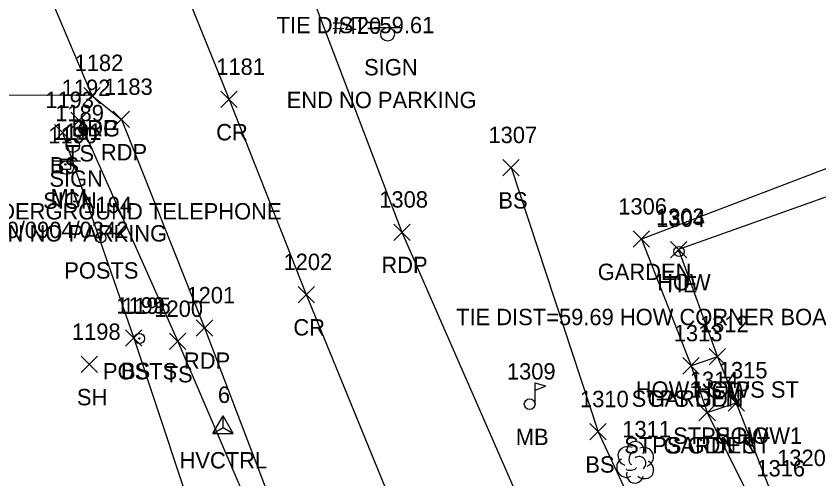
# Model space of a CAD drawing. Extents: x 1651305 to 1654558, y 539481 to 548441.
# Drawn here: x 1654172 to 1654270.1, y 544943.1 to 544999.6 of the extents above; entities that cross this region are included whole.
import ezdxf

# ---------------------------------------------------------------- set-up
doc = ezdxf.new("R2010")
doc.units = 0
for name, color, linetype in [('C_A', 7, 'Continuous'), ('C_C', 7, 'Continuous'), ('C_I', 7, 'Continuous'), ('CBP', 7, 'Continuous'), ('CPSM', 7, 'Continuous'), ('L_A', 7, 'Continuous'), ('L_I', 7, 'Continuous'), ('L_TIC', 7, 'Continuous'), ('LAPB', 7, 'Continuous'), ('LBC', 7, 'Continuous'), ('LBF', 7, 'Continuous'), ('LELB', 7, 'Continuous'), ('LMB', 7, 'Continuous'), ('LPST', 7, 'Continuous'), ('LTD', 7, 'Continuous'), ('P_A', 7, 'Continuous'), ('P_I', 7, 'Continuous'), ('P_TIC', 7, 'Continuous'), ('PET', 7, 'Continuous'), ('PRC', 7, 'Continuous'), ('R_A', 7, 'Continuous'), ('R_I', 7, 'Continuous'), ('R_TIC', 7, 'Continuous'), ('RDG', 7, 'Continuous'), ('S_A', 7, 'Continuous'), ('S_C', 7, 'Continuous'), ('S_I', 7, 'Continuous'), ('SRM', 7, 'Continuous'), ('SSGN', 7, 'Continuous'), ('U_C', 7, 'Continuous')]:
    doc.layers.add(name, color=color, linetype=linetype)

msp = doc.modelspace()

# ---------------------------------------------------------------- linework, layer by layer
at = {"layer": 'CBP'}
for radius in [0.625, 0.0833]:
    msp.add_circle((1654252.972, 544970.875), radius, dxfattribs=at)
at = {"layer": 'CPSM'}
for p, q in [((1654196.041, 544948.65), (1654197.291, 544950.816)), ((1654198.541, 544948.65), (1654197.291, 544950.816)), ((1654197.291, 544949.372), (1654197.291, 544950.816)), ((1654196.041, 544948.65), (1654197.291, 544949.372)), ((1654197.291, 544949.372), (1654197.291, 544949.372)), ((1654197.291, 544949.372), (1654198.541, 544948.65)), ((1654196.041, 544948.65), (1654198.541, 544948.65))]:
    msp.add_line(p, q, dxfattribs=at)
at = {"layer": 'L_TIC'}
for points in [[(1654178.719, 544985.88), (1654180.719, 544987.88)], [(1654180.719, 544985.88), (1654178.719, 544987.88)], [(1654176.711, 544984.406), (1654178.711, 544986.406)], [(1654178.711, 544984.406), (1654176.711, 544986.406)], [(1654231.471, 544980.122), (1654233.471, 544982.122)], [(1654233.471, 544980.122), (1654231.471, 544982.122)], [(1654247.375, 544971.387), (1654249.375, 544973.387)], [(1654249.375, 544971.387), (1654247.375, 544973.387)], [(1654251.913, 544970.116), (1654253.913, 544972.116)], [(1654253.913, 544970.116), (1654251.913, 544972.116)], [(1654185.395, 544959.29), (1654187.395, 544961.29)], [(1654187.395, 544959.29), (1654185.395, 544961.29)], [(1654190.759, 544958.884), (1654192.759, 544960.884)], [(1654192.759, 544958.884), (1654190.759, 544960.884)], [(1654256.648, 544957.011), (1654258.648, 544959.011)], [(1654258.648, 544957.011), (1654256.648, 544959.011)], [(1654256.648, 544957.011), (1654258.648, 544959.011)], [(1654258.648, 544957.011), (1654256.648, 544959.011)], [(1654179.965, 544956.082), (1654181.965, 544958.082)], [(1654181.965, 544956.082), (1654179.965, 544958.082)], [(1654253.449, 544955.905), (1654255.449, 544957.905)], [(1654255.449, 544955.905), (1654253.449, 544957.905)], [(1654253.449, 544955.905), (1654255.449, 544957.905)], [(1654255.449, 544955.905), (1654253.449, 544957.905)], [(1654258.95, 544951.375), (1654260.95, 544953.375)], [(1654260.95, 544951.375), (1654258.95, 544953.375)], [(1654258.95, 544951.375), (1654260.95, 544953.375)], [(1654260.95, 544951.375), (1654258.95, 544953.375)], [(1654255.406, 544950.199), (1654257.406, 544952.199)], [(1654257.406, 544950.199), (1654255.406, 544952.199)], [(1654255.406, 544950.199), (1654257.406, 544952.199)], [(1654257.406, 544950.199), (1654255.406, 544952.199)], [(1654242.092, 544947.856), (1654244.092, 544949.856)], [(1654244.092, 544947.856), (1654242.092, 544949.856)]]:
    msp.add_lwpolyline(points, dxfattribs=at)
at = {"layer": 'LAPB'}
for points in [[(1654280.484, 544984.65), (1654248.375, 544972.387), (1654254.449, 544956.905)], [(1654256.406, 544951.199), (1654262.959, 544938.035), (1654266.98, 544937.971), (1654269.757, 544932.065), (1654277.205, 544934.509)]]:
    msp.add_lwpolyline(points, dxfattribs=at)
at = {"layer": 'LBC'}
msp.add_lwpolyline([(1654281.629, 544981.344), (1654252.913, 544971.116), (1654257.648, 544958.011), (1654259.95, 544952.375), (1654264.598, 544940.395), (1654267.725, 544941.664), (1654270.367, 544934.858), (1654276.314, 544936.878), (1654279.342, 544937.922), (1654288.154, 544941.638), (1654293.107, 544928.35), (1654283.874, 544924.848), (1654288.217, 544913.364), (1654293.485, 544899.631), (1654296.432, 544891.955), (1654318.471, 544900.378)], dxfattribs=at)
at = {"layer": 'LBF'}
msp.add_lwpolyline([(1654257.648, 544958.011), (1654254.449, 544956.905), (1654256.406, 544951.199), (1654259.95, 544952.375)], dxfattribs=at)
at = {"layer": 'LELB'}
for points in [[(1654179.719, 544986.88), (1654191.759, 544959.884), (1654205.631, 544927.6), (1654216.28, 544901.811), (1654236.779, 544849.686), (1654250.25, 544817.938), (1654269.188, 544772.346), (1654285.709, 544732.002), (1654294.184, 544708.026), (1654311.836, 544664.341)], [(1654177.711, 544985.406), (1654186.395, 544960.29), (1654198.077, 544925.069), (1654208.776, 544901.638), (1654231.338, 544847.607), (1654245.847, 544816.464), (1654261.737, 544769.7), (1654274.867, 544730.828), (1654284.44, 544695.192), (1654297.614, 544656.977), (1654309.412, 544642.274)], [(1654232.471, 544981.122), (1654243.092, 544948.856), (1654252.975, 544927.614)]]:
    msp.add_lwpolyline(points, dxfattribs=at)
at = {"layer": 'LMB'}
for p, q in [((1654235.382, 544954.827), (1654236.675, 544954.445)), ((1654235.388, 544952.234), (1654235.386, 544954.829)), ((1654235.386, 544953.927), (1654236.669, 544954.436)), ((1654234.732, 544952.226), (1654234.732, 544952.226))]:
    msp.add_line(p, q, dxfattribs=at)
msp.add_circle((1654234.732, 544952.226), 0.656, dxfattribs=at)
at = {"layer": 'LPST'}
for centre, radius in [((1654182.365, 544972.561), 0.625), ((1654182.365, 544972.561), 0.0833), ((1654187.088, 544960.246), 0.625), ((1654187.088, 544960.246), 0.0833)]:
    msp.add_circle(centre, radius, dxfattribs=at)
at = {"layer": 'LTD'}
msp.add_line((1654247.596, 544945.168), (1654247.596, 544945.168), dxfattribs=at)
msp.add_line((1654247.596, 544945.168), (1654247.596, 544945.168), dxfattribs=at)
msp.add_arc((1654247.642, 544946.602), 1.047, 335.52715, 180.95627, dxfattribs=at)
for centre, major_axis, ratio, start_param, end_param in [((1654246.804, 544945.834), (1.21, -0.512), 0.895232, 1.570796, 4.712389), ((1654248.637, 544945.751), (-1.141, -0.483), 0.949671, 1.570796, 4.712389), ((1654247.387, 544945.626), (-0.208, -0.792), 0.645439, 3.141593, 6.283185), ((1654246.512, 544944.459), (0.584, -1.042), 0.959034, 3.141593, 6.283185), ((1654248.096, 544945.001), (-0.5, 0.667), 0.989748, 3.141593, 6.283185), ((1654248.596, 544944.335), (-1.09, 0.792), 0.841452, 1.570796, 4.712389), ((1654247.137, 544944.418), (-0.625, -0.083), 0.423636, 0, 3.141593), ((1654247.596, 544943.668), (0.265, 1.061), 0.942809, 1.570796, 4.712389)]:
    msp.add_ellipse(centre, major_axis=major_axis, ratio=ratio, start_param=start_param, end_param=end_param, dxfattribs=at)
at = {"layer": 'P_TIC'}
for points in [[(1654180.292, 544988.927), (1654182.292, 544990.927)], [(1654182.292, 544988.927), (1654180.292, 544990.927)], [(1654197.023, 544988.456), (1654199.023, 544990.456)], [(1654199.023, 544988.456), (1654197.023, 544990.456)], [(1654183.888, 544986.01), (1654185.888, 544988.01)], [(1654185.888, 544986.01), (1654183.888, 544988.01)], [(1654218.138, 544972.235), (1654220.138, 544974.235)], [(1654220.138, 544972.235), (1654218.138, 544974.235)], [(1654206.449, 544964.611), (1654208.449, 544966.611)], [(1654208.449, 544964.611), (1654206.449, 544966.611)], [(1654194.032, 544960.541), (1654196.032, 544962.541)], [(1654196.032, 544960.541), (1654194.032, 544962.541)]]:
    msp.add_lwpolyline(points, dxfattribs=at)
at = {"layer": 'PET'}
for points in [[(1654139.13, 545176.501), (1654150.393, 545147.194), (1654157.161, 545131.709), (1654170.764, 545099.134), (1654178.155, 545080.649), (1654186.439, 545060.962), (1654201.827, 545022.365), (1654207.176, 545004.715), (1654219.138, 544973.235), (1654242.36, 544920.072), (1654247.532, 544907.575), (1654259.279, 544878.108), (1654268.455, 544853.759), (1654271.522, 544840.232), (1654282.762, 544813.426), (1654295.449, 544782.265), (1654306.751, 544753.721), (1654320.353, 544717.464), (1654325.712, 544702.64)], [(1654112.873, 545166.538), (1654122.035, 545140.208), (1654132.622, 545111.941), (1654135.362, 545108.194), (1654138.441, 545103.483), (1654151.391, 545069.682), (1654150.584, 545065.43), (1654160.56, 545041.116), (1654174.104, 545006.911), (1654181.292, 544989.927), (1654184.888, 544987.01), (1654195.032, 544961.541), (1654207.758, 544928.164), (1654222.993, 544890.413), (1654239.031, 544850.694), (1654252.069, 544818.679), (1654270.718, 544773.03), (1654287.358, 544732.427), (1654297.759, 544708.463), (1654313.88, 544667.099), (1654319.767, 544684.597), (1654325.712, 544702.64)]]:
    msp.add_lwpolyline(points, dxfattribs=at)
at = {"layer": 'PRC'}
msp.add_lwpolyline([(1654126.316, 545171.737), (1654141.33, 545133.412), (1654151.931, 545107.487), (1654165.206, 545072.693), (1654175.565, 545046.61), (1654188.965, 545011.94), (1654198.023, 544989.456), (1654207.449, 544965.611), (1654220.746, 544933.068), (1654235.659, 544895.022), (1654251.308, 544856.189), (1654265.059, 544822.156), (1654283.023, 544778.205), (1654298.758, 544737.492), (1654308.597, 544712.81), (1654319.767, 544684.597)], dxfattribs=at)
at = {"layer": 'R_TIC'}
for points in [[(1654180.292, 544988.927), (1654182.292, 544990.927)], [(1654182.292, 544988.927), (1654180.292, 544990.927)]]:
    msp.add_lwpolyline(points, dxfattribs=at)
at = {"layer": 'RDG'}
msp.add_lwpolyline([(1654181.292, 544989.927), (1654167.251, 544989.981), (1654154.898, 544987.871), (1654134.518, 544982.897)], dxfattribs=at)
at = {"layer": 'SRM'}
msp.add_lwpolyline([(1654177.431, 544982.142), (1654178.681, 544982.142), (1654178.681, 544980.892), (1654177.431, 544980.892)], close=True, dxfattribs=at)
msp.add_circle((1654178.056, 544981.517), 0.0833, dxfattribs=at)
at = {"layer": 'SSGN'}
for p, q in [((1654215.732, 544998.245), (1654219.065, 544998.245)), ((1654217.379, 544997.412), (1654217.379, 544997.412)), ((1654177.309, 544984.639), (1654180.643, 544984.639)), ((1654178.956, 544983.806), (1654178.956, 544983.806)), ((1654176.549, 544981.949), (1654179.883, 544981.949)), ((1654178.196, 544981.116), (1654178.196, 544981.116))]:
    msp.add_line(p, q, dxfattribs=at)
for centre in [(1654217.379, 544997.412), (1654178.956, 544983.806), (1654178.196, 544981.116)]:
    msp.add_circle(centre, 0.833, dxfattribs=at)

# ---------------------------------------------------------------- texts
at = {"layer": 'C_A'}
for s, p in [('TIE', (1654251.051, 544965.875)), ('HVCTRL', (1654191.984, 544944.372))]:
    msp.add_text(s, height=2, dxfattribs=at).set_placement(p)
at = {"layer": 'C_C'}
for s, p in [('TIE DIST=59.61', (1654203.84, 544997.539)), ('TIE DIST=59.69 HOW CORNER BOARD', (1654225.753, 544961.875))]:
    msp.add_text(s, height=2, dxfattribs=at).set_placement(p)
at = {"layer": 'C_I'}
for s, p in [('1304', (1654250.201, 544973.875)), ('6', (1654196.669, 544952.372))]:
    msp.add_text(s, height=2, dxfattribs=at).set_placement(p)
at = {"layer": 'L_A'}
for s, p in [('TS', (1654178.129, 544981.88)), ('BS', (1654176.152, 544980.406)), ('BS', (1654230.912, 544976.122)), ('POSTS', (1654177.908, 544967.561)), ('GARDEN', (1654243.044, 544967.387)), ('HOW', (1654250.299, 544966.116)), ('POSTS', (1654182.631, 544955.246)), ('BS', (1654184.836, 544955.29)), ('TS', (1654190.168, 544954.884)), ('HOW1 STPS ST', (1654247.688, 544953.011)), ('HOW', (1654255.034, 544953.011)), ('SH', (1654179.453, 544952.082)), ('STPS GDN', (1654247.182, 544951.905)), ('GARDEN', (1654249.119, 544951.905)), ('MB', (1654233.039, 544947.226)), ('STPS HOW1', (1654252.249, 544947.375)), ('HOW', (1654257.336, 544947.375)), ('STPS GDN ST', (1654246.272, 544946.199)), ('GARDEN', (1654251.075, 544946.199)), ('BS', (1654241.533, 544943.856))]:
    msp.add_text(s, height=2, dxfattribs=at).set_placement(p)
at = {"layer": 'L_I'}
for s, p in [('1192', (1654177.594, 544989.88)), ('1193', (1654175.585, 544988.406)), ('1307', (1654229.7, 544984.122)), ('1194', (1654180.239, 544975.561)), ('1306', (1654245.548, 544975.387)), ('1303', (1654250.141, 544974.116)), ('1199', (1654184.262, 544963.29)), ('1195', (1654184.962, 544963.246)), ('1200', (1654188.901, 544962.884)), ('1312', (1654255.522, 544961.011)), ('1312', (1654255.522, 544961.011)), ('1198', (1654178.84, 544960.082)), ('1313', (1654252.324, 544959.905)), ('1313', (1654252.324, 544959.905)), ('1309', (1654231.952, 544955.226)), ('1315', (1654257.825, 544955.375)), ('1315', (1654257.825, 544955.375)), ('1314', (1654254.28, 544954.199)), ('1314', (1654254.28, 544954.199)), ('1310', (1654240.879, 544951.856)), ('1311', (1654246.037, 544948.168)), ('1320', (1654264.946, 544944.664)), ('1316', (1654262.417, 544943.395))]:
    msp.add_text(s, height=2, dxfattribs=at).set_placement(p)
at = {"layer": 'P_A'}
for s, p in [('RDP', (1654178.78, 544984.927)), ('CR', (1654196.456, 544984.456)), ('RDP', (1654182.376, 544982.01)), ('RDP', (1654216.627, 544968.235)), ('CR', (1654205.882, 544960.611)), ('RDP', (1654192.521, 544956.541))]:
    msp.add_text(s, height=2, dxfattribs=at).set_placement(p)
at = {"layer": 'P_I'}
for s, p in [('1182', (1654179.166, 544992.927)), ('1181', (1654196.464, 544992.456)), ('1183', (1654182.762, 544990.01)), ('1308', (1654216.367, 544976.235)), ('1202', (1654204.678, 544968.611)), ('1201', (1654192.828, 544964.541))]:
    msp.add_text(s, height=2, dxfattribs=at).set_placement(p)
at = {"layer": 'R_A'}
msp.add_text('DRG', height=2, dxfattribs=at).set_placement((1654178.78, 544984.927))
at = {"layer": 'R_I'}
msp.add_text('1182', height=2, dxfattribs=at).set_placement((1654179.166, 544992.927))
at = {"layer": 'S_A'}
for s, p in [('SIGN', (1654214.517, 544992.391)), ('SIGN', (1654176.094, 544978.786)), ('MM', (1654176.245, 544976.517)), ('SIGN', (1654175.334, 544976.096))]:
    msp.add_text(s, height=2, dxfattribs=at).set_placement(p)
at = {"layer": 'S_C'}
for s, p in [('END NO PARKING', (1654205.068, 544988.391)), ('WARNING UNDERGROUND TELEPHONE', (1654152.433, 544974.786)), ('1100/0904/0342', (1654166.403, 544972.517)), ('BEGIN NO PARKING', (1654164.61, 544972.096))]:
    msp.add_text(s, height=2, dxfattribs=at).set_placement(p)
at = {"layer": 'S_I'}
for s, p in [('1189', (1654176.803, 544986.786)), ('1191', (1654176.497, 544984.517)), ('1190', (1654175.964, 544984.096))]:
    msp.add_text(s, height=2, dxfattribs=at).set_placement(p)
at = {"layer": 'U_C'}
msp.add_text('#420', height=2, dxfattribs=at).set_placement((1654210.659, 544997.466))

doc.saveas('drawing.dxf')
